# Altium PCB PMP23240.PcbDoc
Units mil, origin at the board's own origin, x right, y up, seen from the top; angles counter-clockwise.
Board outline 2210 x 1500 mil, 2 copper layers (Top Layer, Bottom Layer), stack 62 mil thick; 42 components, 17 nets, 93 pads, 30 vias.
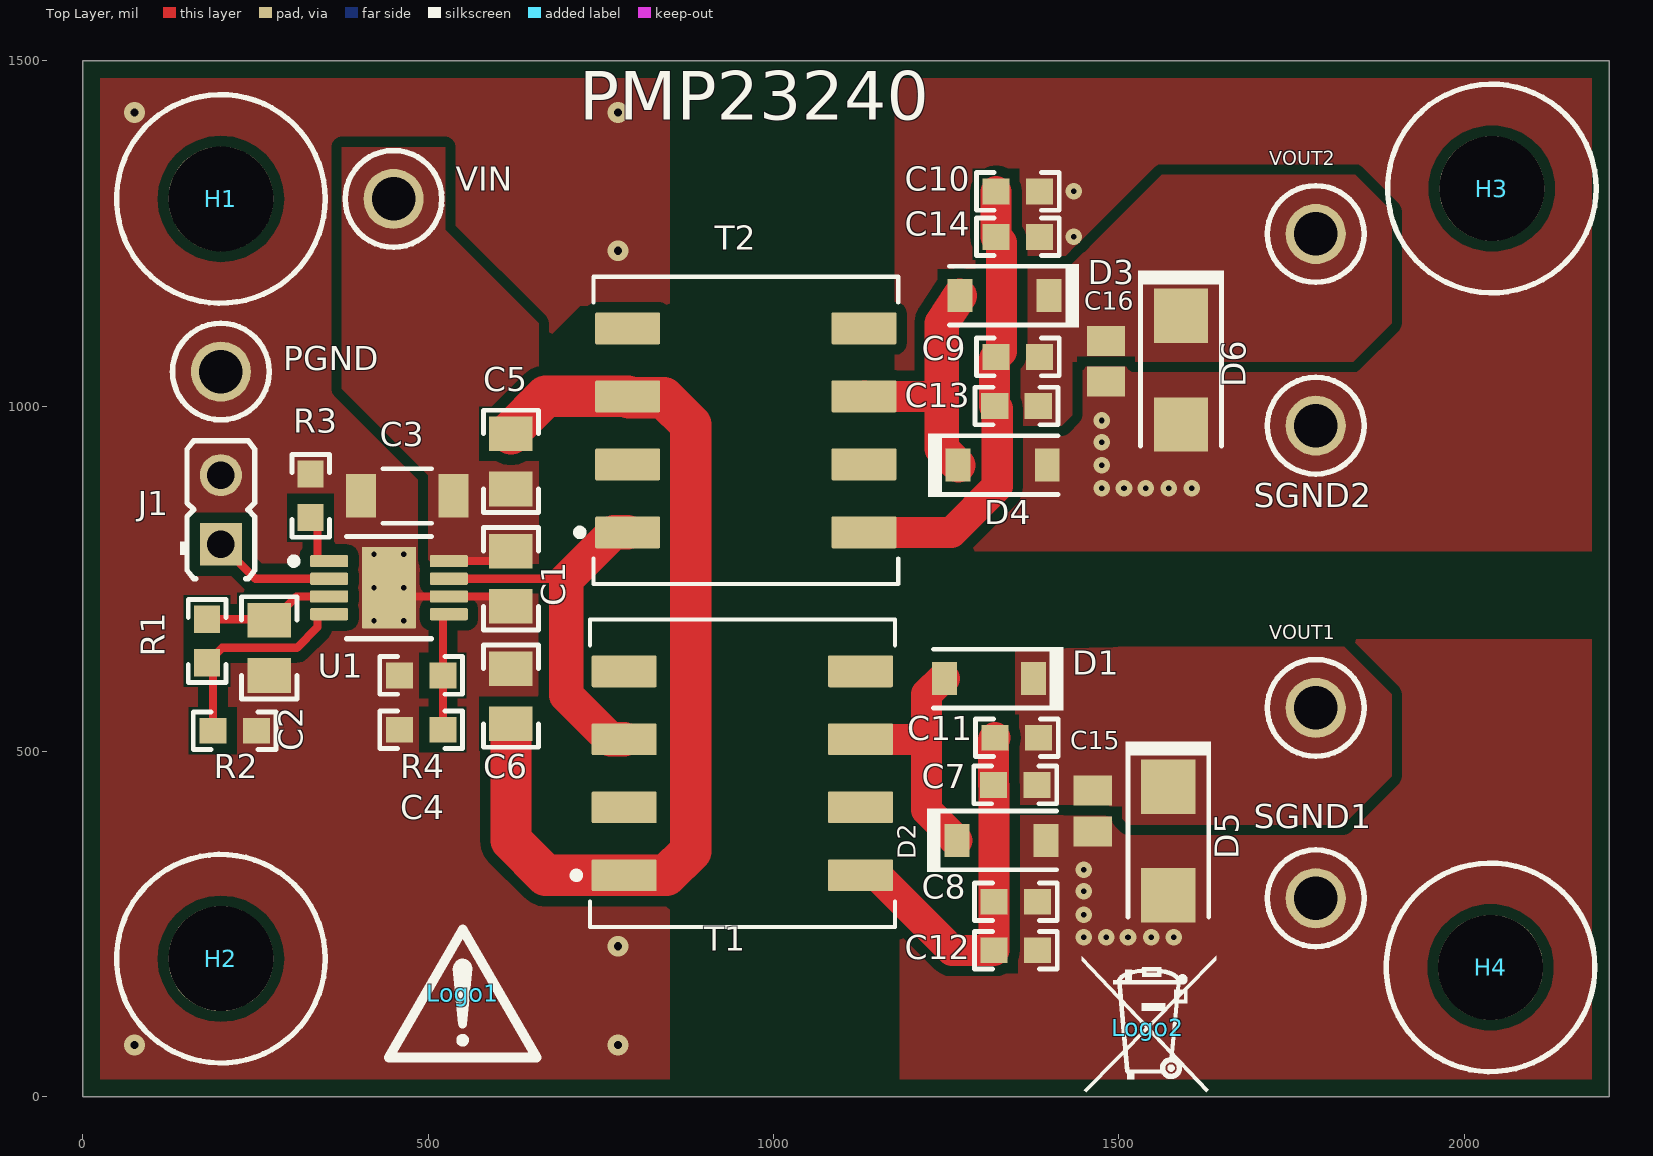
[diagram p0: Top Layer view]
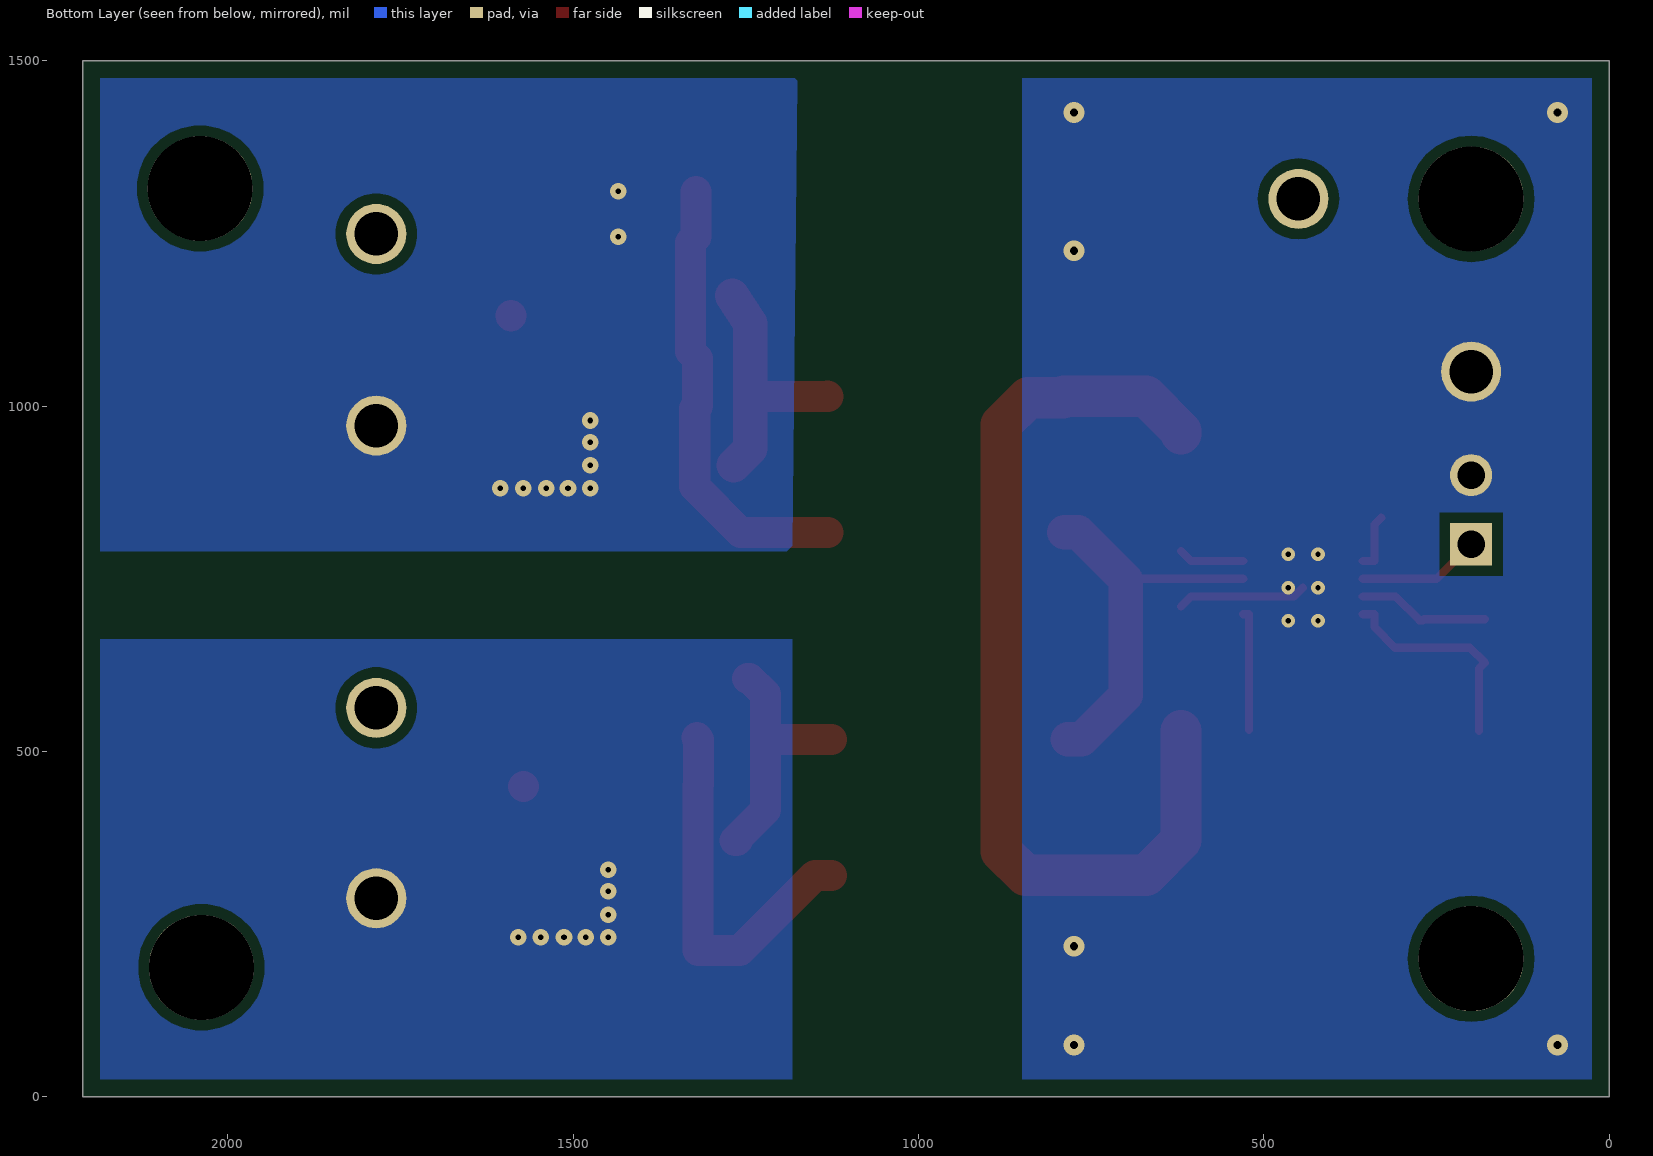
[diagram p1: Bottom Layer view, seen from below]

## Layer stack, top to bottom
Top Solder: solder mask 0.4, Solder Resist, Dk 3.5
Top Layer: signal copper 1.4
Dielectric1: core 59.2, FR-4 High Tg, Dk 4.8
Bottom Layer: signal copper 1.4
Bottom Solder: solder mask 0.4, Solder Resist, Dk 3.5

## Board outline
0,0 0,1500 2210,1500 2210,0

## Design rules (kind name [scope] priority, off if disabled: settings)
AcuteAngle [All] p1: minimum=4.50000000000000E+0001 checktracksonly=FALSE
AssemblyTestPointUsage [All] p1: valid=2
BoardOutlineClearance BoardOutlineClearance_MountingHoles [OnCopper and InComponentClass('Mounting Holes')] p1: gap=25 ignorepadtopadclearanceinfootprint=FALSE
BoardOutlineClearance BoardOutlineClearance_Poly [OnCopper and InPoly] p2: gap=25 ignorepadtopadclearanceinfootprint=FALSE
BoardOutlineClearance [OnCopper and Not InComponentClass('Logo') and not InComponentClass('FiducialMark') and not InRegion(1000,500,4000,800)] p3: gap=25 ignorepadtopadclearanceinfootprint=FALSE
Clearance Clearance_2 [InNetClass('HV') vs Not InNetClass('HV')] p1: gap=60 ignorepadtopadclearanceinfootprint=FALSE
Clearance Clearance_1 [InNetClass('MV') vs Not InNetClass('MV')] p2: gap=30 ignorepadtopadclearanceinfootprint=FALSE
Clearance Clearance_Keepouts [((IsTrack Or IsArc) And Not InPoly) And IsFree and IsKeepOut vs ((IsTrack Or IsArc) And Not InPoly) And IsFree and IsKeepOut] p3: gap=0 ignorepadtopadclearanceinfootprint=FALSE
Clearance Clearance_BoardEdge_MountingHoles [OnCopper and InComponentClass('Mounting Holes') vs IsKeepOut] p4: gap=40 ignorepadtopadclearanceinfootprint=FALSE except(0: Arc-Hole Track-Hole SMDPad-Hole THPad-Hole Via-Hole Fill-Hole Poly-Hole Region-Hole Text-Hole)
Clearance Clearance_BoardEdge_Poly [OnCopper and InPoly vs IsKeepOut] p5: gap=50 ignorepadtopadclearanceinfootprint=FALSE except(0: Arc-Hole Track-Hole SMDPad-Hole THPad-Hole Via-Hole Fill-Hole Poly-Hole Region-Hole Text-Hole)
Clearance Clearance_BoardEdge [OnCopper and Not InComponentClass('Logo') and not InComponentClass('FiducialMark') and not InRegion(1000,500,4000,800) and Not IsKeepout vs IsKeepOut] p6: gap=50 ignorepadtopadclearanceinfootprint=FALSE
Clearance Clearance_Poly [InPolygon] p7: gap=15 ignorepadtopadclearanceinfootprint=FALSE
Clearance [All] p8: gap=7.87 ignorepadtopadclearanceinfootprint=FALSE except(0: Arc-Hole Track-Hole SMDPad-Hole THPad-Hole Via-Hole Fill-Hole Poly-Hole Region-Hole Text-Hole)
ComponentClearance ComponentClearance_MountingHoles_FiducialMarks [InComponentClass('Mounting Holes') vs InComponentClass('FiducialMark')] p1: gap=20 collisioncheckmode=3 verticalgap=10 showdistances=FALSE
ComponentClearance ComponentClearance_Shunt [InComponentClass('Header') vs InComponentClass('Shunt')] p2: gap=0 collisioncheckmode=3 verticalgap=0 showdistances=FALSE
ComponentClearance ComponentClearance_Logo [InComponentClass('Logo')] p3: gap=5 collisioncheckmode=3 verticalgap=10 showdistances=FALSE
ComponentClearance ComponentClearance_ScrewToNut [(HasFootprint('NY PMS 440 0025 PH')) vs (HasFootprint('Keystone_1902C'))] p4: gap=20 collisioncheckmode=3 verticalgap=100000 showdistances=FALSE
ComponentClearance ComponentClearance_MountingHoles [InComponentClass('Mounting Holes')] p5: gap=20 collisioncheckmode=3 verticalgap=10 showdistances=FALSE
ComponentClearance ComponentClearance_SmallPassives [HasFootprint('0201*') or HasFootprint('0402*') or HasFootprint('0508') or HasFootprint('0603*') or HasFootprint('0612') or HasFootprint('0805*') or HasFootprint('0815*') or HasFootprint('0830*') or HasFootprint('1206*') or HasFootprint('1210*') or HasFootprint('1808*') or HasFootprint('1812*') or HasFootprint('1825*') or HasFootprint('2010*') or HasFootprint('2220*') or HasFootprint('2225*') or HasFootprint('2512*') or HasFootprint('2728*') or HasFootprint('3518*') vs HasFootprint('0201*') or HasFootprint('0402*') or HasFootprint('0508') or HasFootprint('0603*') or HasFootprint('0612') or HasFootprint('0805*') or HasFootprint('0815*') or HasFootprint('0830*') or HasFootprint('1206*') or HasFootprint('1210*') or HasFootprint('1808*') or HasFootprint('1812*') or HasFootprint('1825*') or HasFootprint('2010*') or HasFootprint('2220*') or HasFootprint('2225*') or HasFootprint('2512*') or HasFootprint('2728*') or HasFootprint('3518*')] p6: gap=20 collisioncheckmode=3 verticalgap=20 showdistances=FALSE
ComponentClearance ComponentClearance_THtoSMT [IsThruComponent vs IsSMTComponent] p7: gap=10 collisioncheckmode=3 verticalgap=10 showdistances=FALSE
ComponentClearance ComponentClearance_THtoTH [IsThruComponent vs IsThruComponent] p8: gap=10 collisioncheckmode=3 verticalgap=10 showdistances=FALSE
ComponentClearance [All] p9: gap=10 collisioncheckmode=3 verticalgap=10 showdistances=FALSE
DiffPairsRouting [All] p1: maxlimit=100 minlimit=10 mostfreqgap=10 toplayer_minwidth=15 toplayer_maxwidth=15 toplayer_prefwidth=15 bottomlayer_minwidth=15 bottomlayer_maxwidth=15 bottomlayer_prefwidth=15 maxuncoupledlength=1000
FabricationTestPointUsage TestPointUsage [All] p1: valid=2 allowmultiple=FALSE
FabricationTestpoint Testpoint [All] p1: side=3 testpointundercomponent=TRUE minsize=40 maxsize=100 preferedsize=60 minholesize=0 maxholesize=40 preferedholesize=32 testpointgrid=1 allowsidetop=TRUE allowsidebottom=TRUE usegrid=TRUE gridtolerance=0.01
FanoutControl Fanout_LCC [IsLCC] p1: bgadir=Out bgaviamode=Centered fanoutstyle=Auto fanoutdirection=Alternating viagrid=1 // Fanout_LCC (Default Rule)
FanoutControl Fanout_BGA [IsBGA] p2: bgadir=Out bgaviamode=Centered fanoutstyle=Auto fanoutdirection=Alternating viagrid=1 // Fanout_BGA (Default Rule)
FanoutControl Fanout_Default [All] p4: bgadir=Out bgaviamode=Centered fanoutstyle=Auto fanoutdirection=Alternating viagrid=1 // Fanout_Default (Default Rule)
FanoutControl Fanout_Small [(CompPinCount < 5)] p5: bgadir=Out bgaviamode=Centered fanoutstyle=Auto fanoutdirection=OutThenIn viagrid=1 // Fanout_Small (Default Rule)
Height [All] p1: minheight=0 maxheight=3000 prefheight=500
HoleSize [All] p1: absolutevalues=TRUE maxlimit=251 minlimit=7.87 maxpercent=80.000 minpercent=20.000
MinimumAnnularRing MinimumAnnularRing_ThermalPadVias [IsVia and InAnyComponent] p1: minimumring=5.91
MinimumAnnularRing [All] p2: minimumring=8
MinimumSolderMaskSliver MinimumSolderMaskSliver_Logo [InComponentClass('Logo') vs InComponentClass('Logo')] p1: minsoldermaskwidth=0.7
MinimumSolderMaskSliver [All] p2: minsoldermaskwidth=3.94
PlaneConnect [All] p1: planeconnectstyle=Direct reliefexpansion=10 reliefentries=4 reliefconductorwidth=10 reliefairgap=10
PolygonConnect PolygonConnect_15 [All vs IsNamedPolygon('C109_2') Or  IsNamedPolygon('C107_2') Or  IsNamedPolygon('HV') Or  IsNamedPolygon('Q203_5') Or  IsNamedPolygon('C107_2') Or  IsNamedPolygon('HS') Or  IsNamedPolygon('Q201_5') Or  IsNamedPolygon('Q203_5') Or  IsNamedPolygon('C106_2') Or  IsNamedPolygon('C108_2') Or  IsNamedPolygon('Vout') Or  IsNamedPolygon('Q203_5') Or  IsNamedPolygon('C108_2') Or  IsNamedPolygon('C113_2') Or  IsNamedPolygon('Q203_5') Or  IsNamedPolygon('Q201_5') Or  IsNamedPolygon('C107_2') Or  IsNamedPolygon('C102_1') Or  IsNamedPolygon('SGND') Or  IsNamedPolygon('GND') Or  IsNamedPolygon('SGND') Or  IsNamedPolygon('GND') Or  IsNamedPolygon('IN+') Or  IsNamedPolygon('IN+') Or  IsNamedPolygon('Q201_5') Or  IsNamedPolygon('Q201_5') Or  IsNamedPolygon('SGND') Or  IsNamedPolygon('SGND') Or  IsNamedPolygon('Vout') Or  IsNamedPolygon('Vout') Or  IsNamedPolygon('IN+') Or  IsNamedPolygon('GND') Or  IsNamedPolygon('IN+') Or  IsNamedPolygon('GND')] p1: connectstyle=Direct reliefconductorwidth=10 reliefentries=4 polygonreliefangle="90 Angle" airgapwidth=10
PolygonConnect PolygonConnect_14 [All vs IsNamedPolygon('C106_2') Or  IsNamedPolygon('C107_2') Or  IsNamedPolygon('C107_2') Or  IsNamedPolygon('C107_2') Or  IsNamedPolygon('C102_1') Or  IsNamedPolygon('Q203_5') Or  IsNamedPolygon('Vout') Or  IsNamedPolygon('Q203_5') Or  IsNamedPolygon('Q203_5') Or  IsNamedPolygon('Q201_5') Or  IsNamedPolygon('C108_2') Or  IsNamedPolygon('Q203_5') Or  IsNamedPolygon('HS') Or  IsNamedPolygon('HV') Or  IsNamedPolygon('C108_2') Or  IsNamedPolygon('Q201_5') Or  IsNamedPolygon('C109_2') Or  IsNamedPolygon('Q201_5') Or  IsNamedPolygon('Q201_5') Or  IsNamedPolygon('C113_2')] p2: connectstyle=Direct reliefconductorwidth=10 reliefentries=4 polygonreliefangle="90 Angle" airgapwidth=10
PolygonConnect PolygonConnect_13 [All vs IsNamedPolygon('C102_1') Or  IsNamedPolygon('HV') Or  IsNamedPolygon('C107_2') Or  IsNamedPolygon('C109_2') Or  IsNamedPolygon('C107_2') Or  IsNamedPolygon('C108_2') Or  IsNamedPolygon('C106_2') Or  IsNamedPolygon('C108_2') Or  IsNamedPolygon('C113_2') Or  IsNamedPolygon('C107_2')] p3: connectstyle=Direct reliefconductorwidth=10 reliefentries=4 polygonreliefangle="90 Angle" airgapwidth=10
PolygonConnect PolygonConnect_12 [All vs IsNamedPolygon('C107_2') Or  IsNamedPolygon('C113_2') Or  IsNamedPolygon('C106_2') Or  IsNamedPolygon('C107_2') Or  IsNamedPolygon('C107_2') Or  IsNamedPolygon('C102_1')] p4: connectstyle=Direct reliefconductorwidth=10 reliefentries=4 polygonreliefangle="90 Angle" airgapwidth=10
PolygonConnect PolygonConnect_11 [All vs IsNamedPolygon('C106_2') Or  IsNamedPolygon('C102_1') Or  IsNamedPolygon('C107_2') Or  IsNamedPolygon('C107_2') Or  IsNamedPolygon('C107_2')] p5: connectstyle=Direct reliefconductorwidth=10 reliefentries=4 polygonreliefangle="90 Angle" airgapwidth=10
PolygonConnect PolygonConnect_10 [All vs IsNamedPolygon('C106_2')] p6: connectstyle=Direct reliefconductorwidth=10 reliefentries=4 polygonreliefangle="90 Angle" airgapwidth=10
PolygonConnect PolygonConnect_9 [All vs IsNamedPolygon('C11_1') Or  IsNamedPolygon('Vin') Or  IsNamedPolygon('Vin') Or  IsNamedPolygon('5V') Or  IsNamedPolygon('D6_2') Or  IsNamedPolygon('Q3_3') Or  IsNamedPolygon('GND2') Or  IsNamedPolygon('GND2') Or  IsNamedPolygon('GND') Or  IsNamedPolygon('Q3_4') Or  IsNamedPolygon('12V5') Or  IsNamedPolygon('GND') Or  IsNamedPolygon('12V5') Or  IsNamedPolygon('D3_1')] p7: connectstyle=Direct reliefconductorwidth=10 reliefentries=4 polygonreliefangle="90 Angle" airgapwidth=10
PolygonConnect PolygonConnect_8 [All vs IsNamedPolygon('C11_1') Or  IsNamedPolygon('Vin') Or  IsNamedPolygon('12V5') Or  IsNamedPolygon('Q3_3') Or  IsNamedPolygon('GND2') Or  IsNamedPolygon('GND2') Or  IsNamedPolygon('5V') Or  IsNamedPolygon('Q3_4') Or  IsNamedPolygon('12V5')] p8: connectstyle=Direct reliefconductorwidth=10 reliefentries=4 polygonreliefangle="90 Angle" airgapwidth=10
PolygonConnect PolygonConnect_7 [All vs IsNamedPolygon('GND2') Or  IsNamedPolygon('GND2') Or  IsNamedPolygon('5V') Or  IsNamedPolygon('12V5') Or  IsNamedPolygon('12V5') Or  IsNamedPolygon('C11_1')] p9: connectstyle=Direct reliefconductorwidth=10 reliefentries=4 polygonreliefangle="90 Angle" airgapwidth=10
PolygonConnect PolygonConnect_6 [All vs IsNamedPolygon('GND2') Or  IsNamedPolygon('SGND') Or  IsNamedPolygon('GND1') Or  IsNamedPolygon('C901_1') Or  IsNamedPolygon('SGND') Or  IsNamedPolygon('GND2') Or  IsNamedPolygon('GND1')] p10: connectstyle=Direct reliefconductorwidth=10 reliefentries=4 polygonreliefangle="90 Angle" airgapwidth=10
PolygonConnect PolygonConnect_5 [All vs IsNamedPolygon('GND1') Or  IsNamedPolygon('GND1')] p11: connectstyle=Direct reliefconductorwidth=10 reliefentries=4 polygonreliefangle="90 Angle" airgapwidth=10
PolygonConnect PolygonConnect_4 [All vs IsNamedPolygon('C21_1') Or  IsNamedPolygon('C5_1') Or  IsNamedPolygon('C12_2') Or  IsNamedPolygon('C2_2') Or  IsNamedPolygon('C13_1') Or  IsNamedPolygon('C28_1') Or  IsNamedPolygon('C6_1') Or  IsNamedPolygon('GND') Or  IsNamedPolygon('GND2') Or  IsNamedPolygon('C14_1') Or  IsNamedPolygon('C13_1') Or  IsNamedPolygon('Q1_3') Or  IsNamedPolygon('C14_1') Or  IsNamedPolygon('C5_1') Or  IsNamedPolygon('GND2') Or  IsNamedPolygon('C28_1') Or  IsNamedPolygon('D5_2') Or  IsNamedPolygon('D6_2') Or  IsNamedPolygon('D2_1') Or  IsNamedPolygon('C12_2') Or  IsNamedPolygon('D2_1') Or  IsNamedPolygon('C4_1') Or  IsNamedPolygon('C4_1') Or  IsNamedPolygon('C2_2') Or  IsNamedPolygon('GND') Or  IsNamedPolygon('C33_1') Or  IsNamedPolygon('C9_1')] p12: connectstyle=Direct reliefconductorwidth=10 reliefentries=4 polygonreliefangle="90 Angle" airgapwidth=10
PolygonConnect PolygonConnect_3 [All vs IsNamedPolygon('C28_1') Or  IsNamedPolygon('C12_2') Or  IsNamedPolygon('C28_1') Or  IsNamedPolygon('C9_1') Or  IsNamedPolygon('D5_2') Or  IsNamedPolygon('C12_2') Or  IsNamedPolygon('C2_2') Or  IsNamedPolygon('C14_1') Or  IsNamedPolygon('C4_1') Or  IsNamedPolygon('C14_1') Or  IsNamedPolygon('D6_2') Or  IsNamedPolygon('GND2') Or  IsNamedPolygon('Q1_3') Or  IsNamedPolygon('C5_1') Or  IsNamedPolygon('D2_1') Or  IsNamedPolygon('C4_1') Or  IsNamedPolygon('C13_1') Or  IsNamedPolygon('C5_1') Or  IsNamedPolygon('C13_1') Or  IsNamedPolygon('C33_1') Or  IsNamedPolygon('D2_1') Or  IsNamedPolygon('GND') Or  IsNamedPolygon('GND') Or  IsNamedPolygon('GND2') Or  IsNamedPolygon('C2_2') Or  IsNamedPolygon('C6_1') Or  IsNamedPolygon('C21_1')] p13: connectstyle=Direct reliefconductorwidth=10 reliefentries=4 polygonreliefangle="90 Angle" airgapwidth=10
PolygonConnect PolygonConnect_2 [All vs IsNamedPolygon('C21_1') Or  IsNamedPolygon('C4_1') Or  IsNamedPolygon('D5_2') Or  IsNamedPolygon('C5_1') Or  IsNamedPolygon('C14_1') Or  IsNamedPolygon('C13_1') Or  IsNamedPolygon('C4_1') Or  IsNamedPolygon('C33_1') Or  IsNamedPolygon('C12_2') Or  IsNamedPolygon('D2_1') Or  IsNamedPolygon('C2_2') Or  IsNamedPolygon('C28_1') Or  IsNamedPolygon('C12_2') Or  IsNamedPolygon('D2_1') Or  IsNamedPolygon('C5_1') Or  IsNamedPolygon('Q1_3') Or  IsNamedPolygon('GND') Or  IsNamedPolygon('D6_2') Or  IsNamedPolygon('C6_1') Or  IsNamedPolygon('C2_2') Or  IsNamedPolygon('C14_1') Or  IsNamedPolygon('C28_1') Or  IsNamedPolygon('C13_1') Or  IsNamedPolygon('C9_1') Or  IsNamedPolygon('GND')] p14: connectstyle=Direct reliefconductorwidth=10 reliefentries=4 polygonreliefangle="90 Angle" airgapwidth=10
PolygonConnect PolygonConnect_1 [All vs IsNamedPolygon('C28_1') Or  IsNamedPolygon('D5_2') Or  IsNamedPolygon('C5_1') Or  IsNamedPolygon('C5_1') Or  IsNamedPolygon('D2_1') Or  IsNamedPolygon('C21_1') Or  IsNamedPolygon('C9_1') Or  IsNamedPolygon('C4_1') Or  IsNamedPolygon('C14_1') Or  IsNamedPolygon('C28_1') Or  IsNamedPolygon('C6_1') Or  IsNamedPolygon('C12_2') Or  IsNamedPolygon('C33_1') Or  IsNamedPolygon('C4_1') Or  IsNamedPolygon('C13_1') Or  IsNamedPolygon('C12_2') Or  IsNamedPolygon('D6_2') Or  IsNamedPolygon('C2_2') Or  IsNamedPolygon('C14_1') Or  IsNamedPolygon('D2_1') Or  IsNamedPolygon('C2_2') Or  IsNamedPolygon('C13_1')] p15: connectstyle=Direct reliefconductorwidth=10 reliefentries=4 polygonreliefangle="90 Angle" airgapwidth=10
PolygonConnect [All] p16: connectstyle=Direct reliefconductorwidth=10 reliefentries=4 polygonreliefangle="90 Angle" airgapwidth=10
RoutingVias ThermalPadVias [IsVia and InAnyComponent] p1: holewidth=7.87 width=19.68 viastyle="Through Hole" minholewidth=7.87 minwidth=19.68 maxholewidth=12.99 maxwidth=23.62
RoutingVias [All] p2: holewidth=16 width=34 viastyle="Through Hole" minholewidth=7.87 minwidth=20 maxholewidth=40 maxwidth=65
SilkToBoardRegionClearance [Not ((IsComment or IsDesignator) And (Hide <> 'False')) and not InRegion(1000,500,4000,800)] p1:
SilkToSilkClearance SilkToSilkClearance_Pb-FreeLogo [(HasFootprint('Pb-Free_Overlay_Medium') OR HasFootprint('Pb-Free_Overlay_Small')) vs (HasFootprint('Pb-Free_Overlay_Medium') OR HasFootprint('Pb-Free_Overlay_Small'))] p1: silktosilkclearance=0
SilkToSilkClearance [All] p2: silktosilkclearance=4
SilkToSolderMaskClearance SilkToComponentPadClearance [IsPad and InAnycomponent] p1: minsilkscreentomaskgap=5 clearancetoexposedcopper=TRUE
SilkToSolderMaskClearance "Silk to Solder Mask Opening" [All] p2: minsilkscreentomaskgap=4 clearancetoexposedcopper=FALSE
SolderMaskExpansion [All] p1: expansion=1.97 istentingtop=FALSE
Width [All] p1: maxlimit=100 minlimit=6 preferedwidth=10 checkconnectedcopper=TRUE
14 further rules are at their usual default settings.

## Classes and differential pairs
component class Header: J1

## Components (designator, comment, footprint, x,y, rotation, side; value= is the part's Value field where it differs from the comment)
C1 "GRM219R7YA105KA12D" 0805_HV 620,750 r270 top value=1uF
C2 "GRM219R7YA105KA12D" 0805_HV 270,650 r270 top value=1uF
C3 "GRM31CR71H475KA12L" 1206_180 470,870 r180 top value=4.7uF
C4 "GRM1885C1H101JA01D" 0603 490,531.49 r180 top value=100pF
C5 "GRM219R7YA105KA12D" 0805_HV 620,920 r90 top value=1uF
C6 "GRM219R7YA105KA12D" 0805_HV 620,580 r90 top value=1uF
C7 "GRM188R71H223KA01D" 0603 1350.01,451.53 r0 top value=0.022uF
C8 "GRM188R71H223KA01D" 0603 1350.85,282.38 r180 top value=0.022uF
C9 "GRM188R71H223KA01D" 0603 1353.7,1071.07 r0 top value=0.022uF
C10 "GRM188R71H223KA01D" 0603 1353.7,1310.78 r180 top value=0.022uF
C11 "GRM188R71H103KA01D" 0603 1352.4,519.88 r180 top value=0.01uF
C12 "GRM188R71H103KA01D" 0603 1350.85,212.15 r0 top value=0.01uF
C13 "GRM188R71H103KA01D" 0603 1351.74,1000.19 r180 top value=0.01uF
C14 "GRM188R71H103KA01D" 0603 1353.7,1245 r0 top value=0.01uF
C15 "GRM21BZ71E106KE15L" 0805L 1462.2,413.73 r270 top value=10uF
C16 "GRM21BZ71E106KE15L" 0805L 1481.34,1064.9 r270 top value=10uF
D1 "PMEG6010CEGWJ" SOD-123 1311.88,605.59 r180 top value=60V
D2 "PMEG6010CEGWJ" SOD-123 1330.09,371.23 r0 top value=60V
D3 "PMEG6010CEGWJ" SOD-123 1334.47,1160 r180 top value=60V
D4 "PMEG6010CEGWJ" SOD-123 1331.87,914.61 r0 top value=60V
D5 "SMAZ18-13-F" SMA 1571.61,370.42 r270 top value=18V
D6 "SMAZ18-13-F" SMA 1590.01,1052.07 r270 top value=18V
H1 "4824" KEYSTONE_4824 200,1300 r0 top
H2 "4824" KEYSTONE_4824 200,200 r0 top
H3 "4824" KEYSTONE_4824 2040,1315 r0 top
H4 "4824" KEYSTONE_4824 2038.17,187.5 r0 top
J1 "22284023" Molex_0022284023 200,850 r90 top
Logo1 "" IEC_Caution_Small 550,150 r0 top
Logo2 "WEEE logo" WEEE_Minimum 1541.5,100 r0 top
PGND "5011" Keystone5011 200,1050 r90 top
R1 "CRCW06033K24FKEA" 0603 180,660 r90 top value=3.24k
R2 "CRCW060311K0FKEA" 0603 220,530 r180 top value=11.0k
R3 "CRCW060310K0FKEA" 0603 330,870 r270 top value=10.0k
R4 "CRCW060360K4FKEA" 0603 490,610 r0 top value=60.4k
SGND1 "5011" Keystone5011 1785,287.45 r90 top
SGND2 "5011" Keystone5011 1785,971.64 r90 top
T1 "750319177r02" FP-750319177r02_SMT_11MM21_11MM3-MFG 955,468.36 r0 top
T2 "750319177r02" FP-750319177r02_SMT_11MM21_11MM3-MFG 960,964.8 r0 top
U1 "UCC25800DGNRQ1" DGN0008G-MFG 443.39,737.2 r0 top
VIN "5010" Keystone5010 450,1300 r0 top
VOUT1 "5010" Keystone5010 1785,563.09 r0 top
VOUT2 "5010" Keystone5010 1785,1249.2 r0 top

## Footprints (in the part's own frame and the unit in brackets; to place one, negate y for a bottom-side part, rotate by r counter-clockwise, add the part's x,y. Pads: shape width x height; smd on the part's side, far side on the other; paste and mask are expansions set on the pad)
0603 [mm] "0603 from SM-752 data"
  rect 1x0.95 smd: 1(-0.8,0) 2(0.8,0)
  silkscreen extent -1.52,-0.69 1.52,0.69, body extent -0.87,-0.47 0.87,0.47, height 1
0805_HV [mil] "0805 with 30mil clearance between pads"
  rect 50x63 smd: 1(-40,0) 2(40,0)
  silkscreen extent -74,-40 74,40, body extent -43,-29 43,29, height 57
0805L [mm] "0805 from SM-752 data"
  rect 1.1x1.4 smd: 1(-0.75,0) 2(0.75,0)
  body extent -1.1,-0.72 1.1,0.72, height 1.45
1206_180 [mm] "1206_180"
  rect 1.1x1.6 smd: 1(-1.7,0) 2(1.7,0)
  silkscreen extent -0.9,-1 0.9,1, body extent -1.75,-0.95 1.75,0.95, height 1.8
DGN0008G-MFG [mm]
  rrect22% 1.4x0.45 smd paste+0 mask+0: 1(-2.2,0.975) 2(-2.2,0.325) 3(-2.2,-0.325) 4(-2.2,-0.975) 5(2.2,-0.975) 6(2.2,-0.325) 7(2.2,0.325) 8(2.2,0.975)
  rrect5% 2x3 smd paste-1000 mask-1000: 9(0,0)
  silkscreen extent -3.62,-1.88 1.55,1.88, body extent -3,-1.8 3,1.8, height 0.25
FP-750319177r02_SMT_11MM21_11MM3-MFG [mm]
  rrect9% 2.39x1.17 smd paste+0 mask+0: 1(-4.345,-3.75) 2(-4.345,-1.25) 3(-4.345,1.25) 4(-4.345,3.75) 5(4.345,3.75) 6(4.345,1.25) 7(4.345,-1.25) 8(4.345,-3.75)
  silkscreen extent -6.23,-5.65 5.61,5.65, body extent -5.71,-5.75 5.71,5.75, height 0.25
IEC_Caution_Small [mil]
  silkscreen extent -107,-93 107,92
Keystone5010 [mil] "Keystone Multipurpose loops"
  round 87 hole 63: 1(0,0)
  silkscreen extent -70,-70 70,70, body extent -63,-63 63,62, height 319
Keystone5011 [mil] "Keystone Multipurpose loops"
  round 87 hole 63: 1(0,0)
  silkscreen extent -70,-70 70,70, body extent -63,-63 63,62, height 319
KEYSTONE_4824 [mil] "HEX STANDOFF 6-32 NYLON 1-1/2\""
  round 1 on Mech3: 0(0,0)
  round 152 hole 152 unplated: MH(0,0)
  silkscreen extent -151,-151 151,151, body extent -144,-125 144,125, height 1500
Molex_0022284023 [mm] "Header, 2.54mm, 2x1, TH"
  rect 1.55x1.55 hole 1.02: 1(-1.27,0)
  round 1.55 hole 1.02: 2(1.27,0)
  silkscreen extent -2.54,-1.24 2.54,1.5, body extent -2.54,-1.24 2.54,1.24, height 8.4
SMA [mm] "Molded Diode, 2-Leads, Body 4.3x2.6mm, IPC Medium Density, based on OnSemi component dimensions and land pattern"
  rect 2x2 smd: 1(-2,0) 2(2,0)
  silkscreen extent -3.66,-1.57 2.79,1.57, body extent -2.6,-1.3 2.6,1.3, height 2.42
SOD-123 [mm] "On Semi recommended land pattern"
  rect 0.915x1.22 smd: 1(-1.637,0) 2(1.637,0)
  silkscreen extent -2.74,-1.17 2.03,1.17, body extent -1.93,-0.9 1.93,0.9, height 1.35
WEEE_Minimum [mil] "WEEElie bin"
  silkscreen extent -95,-94 99,104

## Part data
C1 C2 C5 C6: library part CMP-0085980-1, "CAP, CERM, 1 µF, 35 V,+/- 10%, X7R, 0805", Cap_Case=0805, Manufacturer=MuRata, TempCo=X7R, Tolerance_%=10%, Value2=35V, ValueDisplayed=1µF
C3: library part CMP-0008969-2, "CAP, CERM, 4.7 uF, 50 V, +/- 10%, X7R, 1206", Cap_Case=2220, Manufacturer=MuRata, Supplier Part Number 1=24R6347, TempCo=X7R, Tolerance_%=10%, Value1=Unknown, Value2=50V, ValueDisplayed=4.7uF
C4: library part CMP-0007171-4, "CAP, CERM, 100 pF, 50 V, +/- 5%, C0G/NP0, 0603", Cap_Case=0603, Manufacturer=MuRata, Supplier Part Number 1=490-1427-1-ND, TempCo=C0G/NP0, Tolerance_%=5%, Value1=Unknown, Value2=50V, ValueDisplayed=100pF
C7 C8 C9 C10: library part CMP-0007444-5, "CAP, CERM, 0.022 uF, 50 V, +/- 10%, X7R, 0603", Cap_Case=0603, Manufacturer=MuRata, Supplier Part Number 1=490-1517-1-ND, TempCo=X7R, Tolerance_%=10%, Value1=Unknown, Value2=50V, ValueDisplayed=0.022uF
C11 C12 C13 C14: library part CMP-0007433-4, "CAP, CERM, 0.01 uF, 50 V, +/- 10%, X7R, 0603", Cap_Case=0603, Manufacturer=MuRata, Supplier Part Number 1=490-1512-1-ND, TempCo=X7R, Tolerance_%=10%, Value1=Unknown, Value2=50V, ValueDisplayed=0.01uF
C15 C16: library part CMP-0008378-2, "CAP, CERM, 10 uF, 25 V, +/- 10%, X7R, 0805", Cap_Case=0805, Manufacturer=MuRata, Supplier Part Number 1=81-GRM21BZ71E106KE5L, TempCo=X7R, Tolerance_%=10%, Value1=Unknown, Value2=25V, ValueDisplayed=10uF
D1 D2 D3 D4: library part CMP-0079239-2, "Diode, Schottky, 60 V, 1 A, AEC-Q101, SOD-123", Manufacturer=Nexperia, Value1=1A, Value2=0.66V
D5 D6: library part CMP-0005526-4, "Diode, Zener, 18 V, 1 W, AEC-Q101, SMA", Manufacturer="Diodes Inc.", Power_W=1W
H1 H2 H3 H4: library part CMP-0003690-1, Manufacturer=Keystone, Supplier Part Number 1=36-4824-ND
J1: library part CMP-0055333-1, "Header, 2.54mm, 2x1, Tin, TH", Color=Black, Current_A=4A, Manufacturer=Molex, Supplier Part Number 1=WM50016-02-ND, Voltage_V=250V
Logo1: library part CMP-0074836-1, "IEC 61010-1 Caution Warning", PartNumber="CAUTION.  READ USER GUIDE BEFORE USE"
Logo2: library part CMP-0074769-1
PGND SGND1 SGND2: library part CMP-0055148-1, "Test Point, Multipurpose, Black, TH", Color=Black, Manufacturer=Keystone, Supplier Part Number 1=36-5011-ND
R1: library part CMP-0022374-4, "RES, 3.24 k, 1%, 0.1 W, AEC-Q200 Grade 0, 0603", Manufacturer=Vishay-Dale, Power_W=100mW, Supplier Part Number 1=541-3.24KHCT-ND, TempCo="100 ppm/C", Tolerance_%=1%, Value2=0.1W, Value_Code=3k24, ValueDisplayed=3.24k
R2: library part CMP-0022016-4, "RES, 11.0 k, 1%, 0.1 W, AEC-Q200 Grade 0, 0603", Manufacturer=Vishay-Dale, Power_W=100mW, Supplier Part Number 1=541-11.0KHCT-ND, TempCo="100 ppm/C", Tolerance_%=1%, Value2=0.1W, Value_Code=11k0, ValueDisplayed=11.0k
R3: library part CMP-0021998-4, "RES, 10.0 k, 1%, 0.1 W, AEC-Q200 Grade 0, 0603", Manufacturer=Vishay-Dale, Power_W=100mW, Supplier Part Number 1=541-10.0KHCT-ND, TempCo="100 ppm/C", Tolerance_%=1%, Value2=0.1W, Value_Code=10k0, ValueDisplayed=10.0k
R4: library part CMP-0022532-4, "RES, 60.4 k, 1%, 0.1 W, AEC-Q200 Grade 0, 0603", Manufacturer=Vishay-Dale, Power_W=100mW, Supplier Part Number 1=541-60.4KHCT-ND, TempCo="100 ppm/C", Tolerance_%=1%, Value2=0.1W, Value_Code=60k4, ValueDisplayed=60.4k
T1 T2: library part CMP-0091345-1, "Transformer, 1:1.67, 0.045Ohm Pri, 0.122Ohm Sec, 16.5uH", Frequency_Fixed=500kHz, Manufacturer="Wurth Electronics", Operating Temperature Range="-40°C to +125°C"
U1: library part CMP-0088494-2, "Open Loop LLC Transformer Driver for Isolated Bias Supplies", Manufacturer="Texas Instruments", Max Supply Voltage=36V, Min Supply Voltage=12V, Nominal Supply Current=500uA, Operating Temperature Range="-40°C to +150°C", Switching Frequency=100-2000kHz
VIN VOUT1 VOUT2: library part CMP-0055147-1, "Test Point, Multipurpose, Red, TH", Color=Red, Manufacturer=Keystone, Supplier Part Number 1=36-5010-ND

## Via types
v1: diameter 24, hole 8, Top Layer to Bottom Layer, tented both sides, 18 vias
v2: diameter 30, hole 12, Top Layer to Bottom Layer, tented top, 6 vias
v3: diameter 19.68, hole 7.87, Top Layer to Bottom Layer, 6 vias

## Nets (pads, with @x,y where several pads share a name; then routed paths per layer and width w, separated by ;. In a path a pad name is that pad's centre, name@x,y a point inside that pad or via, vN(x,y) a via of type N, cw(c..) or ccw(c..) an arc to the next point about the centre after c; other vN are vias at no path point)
+12V: C1.1 C3.1 C5.1 U1.8 VIN.1 | length 96
  Top Layer w12: U1.8 605.59,775.59 C1.1
NetC2_1: C2.1 R1.2 U1.3 | length 191.6
  Top Layer w12: R1.2 268.5,691.5 C2.1 275,690 309.41,724.41 U1.3
NetC4_1: C4.1 R4.2 U1.5 | length 175.8
  Top Layer w12: C4.1 521.5,698.82 U1.5
NetC5_2: C5.2 C6.1 T1.1 T2.3 | length 1373
  Top Layer w60: C6.1@620,530 620,371.23 670.51,320.72 T1.1 844.85,320.72 880,355.87 880,973.34 841.22,1012.12 790.83,1012.12 T2.3 670.51,1014.01 620,963.5 C5.2
NetC7_1: C7.1 C8.2 C11.2 C12.1 T1.8 | length 547.3
  Top Layer w45: T1.8 1150.08,320.72 1258.65,212.15 C12.1 C8.2 1319.36,450.68 C7.1 1318.51,517.49 C11.2
NetC7_2: C7.2 C11.1 C15.1 D1.1 D5.1 VOUT1.1 | length 0
NetC9_1: C9.1 C10.2 C13.2 C14.1 T2.8 | length 656.6
  Top Layer w45: T2.8 1257.66,817.16 1323.96,883.46 1323.96,996.47 C13.2 1320.24,1069.11 1330.09,1078.95 1330.09,1237.12 C14.1 C10.2
NetC9_2: C9.2 C13.1 C16.1 D3.1 D6.1 VOUT2.1 | length 0
NetD1_2: D1.2 D2.1 T1.6 | length 362.3
  Top Layer w45: T1.6 1221.76,517.57 ; D1.2 1244.44,605.59 1221.76,582.91 1221.76,517.57 ; D2.1 1262.65,371.23 1261.13,372.75 1261.13,375.72 1221.76,415.09 1221.76,517.57
NetD3_2: D3.2 D4.1 T2.6 | length 378.5
  Top Layer w45: T2.6@1131.59,1014.55 T2.6 1239,1014.01 1243.87,1018.89
  Top Layer w50: D4.1 1243.87,938.14 1243.87,1018.89 1243.87,1120.22 D3.2
NetJ1_1: J1.1 U1.2 | length 177.5
  Top Layer w12: J1.1 249.99,750 U1.2
NetR1_1: R1.1 R2.2 U1.4 | length 318.9
  Top Layer w12: R2.2 188.5,620 R1.1 201.5,650 310,650 340,680 340,698.82 U1.4
NetR3_2: R3.2 U1.1 | length 83.8
  Top Layer w12: R3.2 340,828.5 340,775.59 U1.1
NetT1_3: T1.3 T2.1 U1.7 | length 583.2
  Top Layer w12: U1.7 701.69,750 718.5,750
  Top Layer w50: T1.3 763.86,517.57 700,581.43 700,748.3 701.69,750 768.86,817.16 T2.1
PGND: C1.2 C2.2 C3.2 C4.2 C6.2 J1.2 PGND.1 R2.1 R3.1 R4.1 U1.6 U1.9 | length 187.9
  Top Layer w12: U1.9 456.18,724.41 U1.6 605.59,724.41 C1.2
  other v2: 75,75 775,75 775,217.84 775,1225 75,1425 775,1425
  other v3: 421.73,689.17 465.04,689.17 421.73,737.2 465.04,737.2 421.73,785.24 465.04,785.24
SGND1: C8.1 C12.2 C15.2 D2.2 D5.2 SGND1.1
  other v1: 1449.41,230.85 1481.89,230.85 1513.25,230.84 1546.94,230.84 1579.77,230.84 1449.41,263.68 1449.41,297.37 1449.42,328.73
SGND2: C10.1 C14.2 C16.2 D4.2 D6.2 SGND2.1
  other v1: 1474.99,881.26 1507.47,881.26 1538.83,881.25 1572.53,881.25 1605.35,881.25 1474.99,914.09 1474.99,947.78 1475,979.14 1435,1245 1435,1310.78
pads on no net: H1.0 H1.MH H2.0 H2.MH H3.0 H3.MH H4.0 H4.MH T1.2 T1.4 T1.5 T1.7 T2.2 T2.4 T2.5 T2.7

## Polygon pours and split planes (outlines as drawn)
SGND1 on Top Layer "TOP_LAYER_SGND1_P036" (solid, remove dead copper, pour order 36): 1183.17,662.59 1183.17,636.2 1183.17,0 2210,0 2210,662.59
SGND2 on Top Layer "TOP_LAYER_SGND2_P035" (solid, remove dead copper, pour order 35): 1175.67,1500 1175.67,805 1190.67,790 2210,790 2210,1500
NetC7_2 on Top Layer "TOP_LAYER_NETC7_2_P034" (solid, remove dead copper, pour order 34): 1495.72,651.59 1826.32,651.59 1895,582.91 1895,464.33 1824.72,394.05 1526.29,394.05
NetC9_2 on Top Layer "TOP_LAYER_NETC9_2_P033" (solid, remove dead copper, pour order 33): 1429.47,1202.5 1561.97,1335 1842.24,1335 1895,1282.24 1895,1120 1839,1064 1568.34,1064
NetC7_2 on Top Layer "TOP_LAYER_NETC7_2_P032" (solid, remove dead copper, pour order 32): 1353.7,648.09 1350.01,644.4 1350.01,422.98 1484.45,422.98 1513.39,394.05 1630.12,394.05 1630.12,547.76 1526.29,651.59
NetC9_2 on Top Layer "TOP_LAYER_NETC9_2_P031" (solid, remove dead copper, pour order 31): 1351.74,1202.68 1351.74,971.64 1417.21,971.64 1432.2,986.64 1432.2,1064 1658,1064 1658.9,1064.9 1658.9,1178.78 1635,1202.68
PGND on Top Layer "Top Layer-No Net 6" (solid, remove dead copper, pour order 2): 0,1500 850,1500 850,1145 720,1145 660,1085 660,415 720,355 850,355 850,0 0,0
+12V on Top Layer "Top Layer-No Net 6" (solid, remove dead copper, pour order 0): 375,1375 525,1375 525,1255 660,1120 660,760 500.08,760 500.08,899.91 375,1024.99
SGND1 on Bottom Layer "BOTTOM_LAYER_SGND1_P038" (solid, remove dead copper, pour order 38): 1183.17,25.49 2184.51,25.49 2184.51,662.59 1183.17,662.59
SGND2 on Bottom Layer "BOTTOM_LAYER_SGND2_P037" (solid, remove dead copper, pour order 37): 1175.67,1474.51 2184.51,1474.51 2184.51,790 1190.67,790 1183.17,797.5
PGND on Bottom Layer "Top Layer-No Net 6" (solid, remove dead copper, pour order 4): 0,1500 850,1500 850,0 0,0

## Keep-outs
Keep-Out Layer:
  text ".Layer_Name" at 577,-858.49 h60

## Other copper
Top Layer:
  text ".Layer_Name" at 577,-858.49 h60
Bottom Layer:
  text ".Layer_Name" at 577,-858.49 h60

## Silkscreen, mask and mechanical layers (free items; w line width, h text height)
Top Overlay:
  text "PMP23240" at 718.5,1391.44 h120
  text ".Layer_Name" at 577,-858.49 h60
Bottom Overlay:
  text ".Layer_Name" at 577,-858.49 h60
Top Paste:
  text ".Layer_Name" at 577,-858.49 h60
Bottom Paste:
  text ".Layer_Name" at 577,-858.49 h60
Top Solder:
  text ".Layer_Name" at 577,-858.49 h60
  text ".Layer_Name" at 577,-858.49 h60
Bottom Solder:
  text ".Layer_Name" at 577,-858.49 h60
Drill Guide:
  text ".Layer_Name" at 577,-858.49 h60
M1 Board Outline:
  the board outline again, w10
  text ".Layer_Name" at 577,-858.49 h60
M2 Board Dimensions:
  rectangle: 0,-275 125,-150
  rectangle: 125,-400 500,-275
  lines w7: 0,-275 1000,-275 ; 125,-400 125,-150 ; 250,-400 250,-150 ; 500,-400 500,-150 ; 750,-400 750,-150 ; 0,-400 1000,-400 1000,-150 0,-150 0,-400
  text ".Layer_Name" at 577,-858.49 h60
M3 3D STEP Top:
  text ".Layer_Name" at 577,-858.49 h60
M4 3D STEP Bottom:
  text ".Layer_Name" at 577,-858.49 h60
M5 Assembly Top:
  lines w10: -292,-930.17 6308,-930.17 ; -292,-726.83 6310,-726.83 ; -292,-523.5 -292,-1133.5 3713,-1133.5 6310,-1133.5 6310,-523.5 -291.5,-523.5 -291.5,-1133.5 1284,-1133.5 ; 2173,-1133.5 2173,-523.5 ; 3440,-726.83 3440,-523.5 ; 4280,-726.83 4280,-523.5 ; 4902,-1140 4902,-937.17
  text "COMPONENTS MARKED 'DNP' SHOULD NOT BE POPULATED." at 1153.5,-318.5 h60
  text "ASSEMBLY VARIANT:" at 1153,-434 h60
  text ".VariantName" at 2189,-434 h60
  text "PCB VIEWED FROM TOP SIDE" at -228.5,-655.67 h60
  text "BOARD #:" at 2248,-655.67 h60
  text ".PRJ_Number" at 2793.5,-655.67 h60
  text "REV:" at 3638,-655.67 h60
  text ".PCB_Rev" at 3929.5,-655.67 h60
  text "SVN REV:" at 4476,-655.67 h60
  text ".VersionControl_RevNumber" at 4982,-655.67 h60
  text "TID #:" at 2248,-859 h60
  text ".TID" at 2793.5,-859 h60
  text "PLOT NAME =" at -228.5,-1064.34 h60
  text ".plot_File_Name" at 577,-1064.34 h60
  text "GENERATED    :" at 2250,-1064.34 h60
  text ".Print_Date" at 3119.5,-1064.34 h60
  text ".Print_Time" at 3848.5,-1064.34 h60
  text "TEXAS INSTRUMENTS" at 5113,-1064.34 h60
M6 Assembly Bottom:
  lines w10: -292.5,-727.33 6309.5,-727.33 ; -290.5,-930.67 6309.5,-930.67 ; 1115.5,-1140.5 1115.5,-937.67 ; 1737.5,-727.33 1737.5,-524 ; 2577.5,-727.33 2577.5,-524 ; 3844.5,-1134 3844.5,-524 ; 4733.5,-1134 6309,-1134 6309,-524 -292.5,-524 -292.5,-1134 2304.5,-1134 6309.5,-1134 6309.5,-524
  text "COMPONENTS MARKED 'DNP' SHOULD NOT BE POPULATED." at 6102,-318 h60
  text ".VariantName" at 5058,-434 h60
  text "ASSEMBLY VARIANT:" at 6097,-434 h60
  text ".VersionControl_RevNumber" at 1035.5,-656.17 h60
  text "SVN REV:" at 1541.5,-656.17 h60
  text ".PCB_Rev" at 2088,-656.17 h60
  text "REV:" at 2379.5,-656.17 h60
  text ".PRJ_Number" at 3224,-656.17 h60
  text "BOARD #:" at 3769.5,-656.17 h60
  text "PCB VIEWED FROM BOTTOM SIDE" at 6246,-656.17 h60
  text ".TID" at 3224,-859.5 h60
  text "TID #:" at 3769.5,-859.5 h60
  text "TEXAS INSTRUMENTS" at 904.5,-1064.84 h60
  text ".Print_Time" at 2169,-1064.84 h60
  text ".Print_Date" at 2898,-1064.84 h60
  text "GENERATED    :" at 3767.5,-1064.84 h60
  text ".plot_File_Name" at 5440.5,-1064.84 h60
  text "PLOT NAME =" at 6246,-1064.84 h60
M9 Title Sheet:
  drawing of 57 lines, arcs and shapes, not listed
  text "1" at 739.84,8036.5 h70
  text "2" at 3235.5,8036.5 h70
  text "3" at 5724.84,8036.5 h70
  text "4" at 8231.51,8036.5 h70
  text "5" at 10730.5,8036.5 h70
  text "6" at 13235.5,8036.5 h70
  text "A" at -416.5,6893.5 h70
  text "A" at 14383.5,6893.5 h70
  text "B" at -416.5,4513.5 h70
  text "B" at 14383.5,4513.5 h70
  text "C" at -416.5,2138.5 h70
  text "C" at 14383.5,2138.5 h70
  text "PROJECT TITLE:" at 11343.5,277.5 h45
  text ".PRJ_Title" at 11393.5,144.17 h70
  text "DESIGNED FOR:" at 11343.5,-23.5 h45
  text ".PRJ_Customer" at 11393.5,-163.5 h70
  text "D" at -416.5,-231.5 h70
  text "D" at 14383.5,-231.5 h70
  text "FILE NAME:" at 11343.5,-323.5 h45
  text ".PCB_File_Name_No_Path" at 11393.5,-443.5 h70
  text "Texas Instruments (TI) and/or its licensors do not warrant the accuracy or completeness of this specification" at 6374,-605.34 h45
  text "ENGINEER:" at 11343.5,-613.5 h45
  text "LAYOUT BY:" at 12848.5,-613.5 h45
  text "or any information contained therein. TI and/or its licensors do not warrant that this design will meet" at 6329.01,-718 h45
  text ".PRJ_Engineer" at 11393.5,-768.49 h70
  text ".PCB_Layout" at 12899,-768.49 h70
  text "the specifications, will be suitable for your application or fit for any particular purpose, or will operate in" at 6329.01,-830.67 h45
  text ".Layer_Name" at 577,-858.49 h60
  text "ALTIUM DESIGNER VERSION:" at 12848.5,-923.5 h45
  text "an implementation. TI and/or its licensors do not warrant that the design is production worthy. You should" at 6329.01,-943.33 h45
  text "completely validate and test your design implementation to confirm the system functionality for your application." at 6374,-1056 h45
  text ".print_Scale" at 11393.5,-1056.83 h70
  text ".Application_BuildNumber" at 12899,-1056.83 h70
  text "1" at 739.84,-1263.5 h70
  text "2" at 3235.5,-1263.5 h70
  text "3" at 5724.84,-1263.5 h70
  text "4" at 8231.51,-1263.5 h70
  text "5" at 10730.5,-1263.5 h70
  text "6" at 13235.5,-1263.5 h70
M10 Fab Notes:
  drawing of 189 lines, arcs and shapes, not listed
  text "DESIGN INFORMATION" at 12382.02,6356.17 h60
  text "MIN. TRACK WIDTH:" at 11737.46,6224.05 h60
  text "8" at 12833.7,6224.05 h60
  text "MIL" at 12988.46,6224.05 h60
  text "7.874" at 12667.32,6102.36 h60
  text "MIN. CLEARANCE:" at 11737.46,6099.92 h60
  text "MIL" at 12988.46,6099.92 h60
  text "MIN. VIA PAD SIZE:" at 11737.46,5975.8 h60
  text "24" at 12803.71,5975.8 h60
  text "MIL" at 12988.46,5975.8 h60
  text "0.05mm (2MIL)" at 12432.46,5845.9 h60
  text "MINIMUM ANNULAR RING" at 11408.23,5837.67 h60
  text "EXTERNAL" at 13140.46,5837.67 h60
  text "PER" at 11608.23,5727.55 h60
  text "IPC-D-275 CLASS 2 LEVEL C" at 11828.23,5727.54 h60
  text "MIL, HOLES" at 13316.46,5627.07 h60
  text "+/-" at 12924,5618.48 h60
  text "+/-" at 13778,5618.48 h60
  text "REGISTRATION TOLERANCES:" at 11408.23,5617.42 h60
  text "METAL" at 12608,5617.42 h60
  text "5" at 13184.2,5617.42 h60
  text "3" at 14017.2,5617.42 h60
  text "MIL" at 14133.46,5617.42 h60
  text "HOLE SIZE TOLERANCE (UNLESS OTHERWISE SPECIFIED):" at 11408.23,5519.1 h60
  text "+/-" at 13778,5516.23 h60
  text "3" at 14017.2,5515.17 h60
  text "MIL" at 14133.46,5515.17 h60
  text "MATERIAL:" at 11333.46,5377.52 h60
  text "FR-4 High Tg" at 12319.9,5249 h60
  text "X" at 12175.46,5241.01 h60
  text "FR-408" at 11754.46,5236.49 h60
  text "OTHER" at 13242.46,5236.49 h60
  text "62 MIL (1.6mm) +/-10%" at 12074.56,5093.46 h60
  text "X" at 11954.46,5091.01 h60
  text "THICKNESS:" at 11408.23,5085.24 h60
  text "OTHER" at 13359.46,5085.24 h60
  text "TOLERANCE:" at 11408.23,4946.92 h60
  text "X" at 12256.46,4946.92 h60
  text "ANSI IPC-6012 TYPE 3 CLASS 2" at 12434.48,4946.92 h60
  text "OTHER +/-" at 12434.46,4802.73 h60
  text "BOW & TWIST:" at 11408.23,4657.54 h60
  text "X" at 12256.46,4657.54 h60
  text "ANSI IPC-6012 TYPE 3 CLASS 2" at 12434.48,4657.54 h60
  text "OTHER +/-" at 12434.46,4510.85 h60
  text "DRILLING:" at 11333.46,4380.23 h60
  text "NC_DRILL FILES" at 13094.46,4275.04 h60
  text "REFERENCE:" at 11408.23,4271.1 h60
  text "X" at 12065.46,4271.01 h60
  text "AS SHOWN" at 12243.46,4271.1 h60
  text "X" at 12966.46,4271.1 h60
  text "OTHER" at 13392.46,4128.85 h60
  text "PTH COPPER THICKNESS:" at 11407.91,4125.32 h60
  text "X" at 12547.14,4125.32 h60
  text "20-30 um" at 12675.14,4125.32 h60
  text "BOARD FINISH:" at 11333.46,3977.73 h60
  text "SILKSCREEN:" at 11488.68,3867.6 h60
  text "X" at 12446.46,3867.6 h60
  text "TOP" at 12563.46,3867.6 h60
  text "X" at 12956.46,3867.6 h60
  text "BOTTOM" at 13074.46,3867.6 h60
  text "SILKSCREEN COLOR:" at 11488.68,3712.41 h60
  text "X" at 12445.46,3712.41 h60
  text "WHITE" at 12563.46,3712.41 h60
  text "OTHER" at 13074.46,3712.41 h60
  text "X" at 12576.46,3568.96 h60
  text "GREEN" at 12694.46,3568.96 h60
  text "OTHER" at 13312.46,3568.96 h60
  text "SOLDER RESIST COLOR:" at 11488.68,3562.1 h60
  text "X" at 12576.46,3414.71 h60
  text "MATTE" at 12694.46,3414.71 h60
  text "SEMI-GLOSS" at 13312,3414.07 h60
  text "IMMERSION GOLD (ENIG)" at 12394.46,3241.94 h60
  text "ENEPIG" at 13732,3234.72 h60
  text "SURFACE FINISH:" at 11333.46,3233.72 h60
  text "X" at 12216.46,3233.72 h60
  text "IMM. TIN/SILVER OR EQUIV" at 11663,3096.4 h60
  text "OTHER" at 13094.46,3092.47 h60
  text "ARRAY/PANEL:" at 11333.46,2937.09 h60
  text "CUT AND TRIM PER M1 BOARD OUTLINE" at 12394.46,2928.87 h60
  text "N.C. ROUTE" at 12394.46,2792.9 h60
  text "X" at 13082.46,2792.9 h60
  text "V. SCORE" at 13260.46,2792.9 h60
  text "CERTIFICATION:" at 11333.46,2663.77 h60
  text "MATERIALS AND WORKMANSHIP FOR ALL PCBS" at 12058.46,2663.77 h60
  text "TO MEET OR EXCEED THE REQUIREMENTS OF:" at 12058.46,2569.71 h60
  text "X" at 11695.97,2441.08 h60
  text "ANSI IPC-A-600F CLASS ->" at 11823.96,2441.08 h60
  text "X" at 13471.97,2441.08 h60
  text "2" at 13581.96,2441.08 h60
  text "1" at 13266.96,2439.58 h60
  text "3" at 13935.96,2439.58 h60
  text "X" at 12507.97,2293.39 h60
  text "RoHS" at 12635.96,2293.39 h60
  text "OTHER" at 13280.36,2293.39 h60
  text "PER ORDER" at 13677.42,2293.39 h60
  text "ALL BOARDS MUST MEET OR EXCEED UL94-V0 REQUIREMENTS." at 11361,2139.57 h60
  text "PCB MUST BEAR THE UL94V-0 UL REGISTERED MATERIAL ID NUMBER" at 11361,2023.5 h60
  text "ADDITIONAL REQUIREMENTS:" at 11333.46,1854.08 h60
  text "MICROSECTION:" at 11408.23,1746.95 h60
  text "YES" at 12313.96,1746.95 h60
  text "REQUIRED" at 13175.46,1602.62 h60
  text "BARE BOARD ELEC. TEST:" at 11408.23,1599.76 h60
  text "NONE" at 12713.96,1599.76 h60
  text "X" at 13057.46,1599.76 h60
  text "PER ORDER" at 13767.46,1599.76 h60
  text "XX MIL VIAS REQUIRE NON-CONDUCTIVE FILL AND PLANARIZE" at 11576.38,1394.82 h59
  text "XX MIL VIAS REQUIRE CONDUCTIVE FILL AND PLANARIZE" at 11584.38,1290.84 h60
  text "OUTER XX MIL TRACES REQUIRE 50 OHM SINGLE-ENDED IMPEDANCE" at 11583.39,1127.46 h58
  text "LAYER 2 & 3 (INNER LAYERS) XX MIL WIDE, XX MIL SPACE / TRACES REQUIRE 100 OHM DIFFERENTIAL IMPEDANCE" at 11575.39,891.74 h60
  text ".Layer_Name" at 577,-858.49 h60
M11 Gerber Information:
  lines w10: -292,-930.17 6308,-930.17 ; -292,-726.83 6310,-726.83 ; -292,-523.5 -292,-1133.5 3713,-1133.5 6310,-1133.5 6310,-523.5 -291.5,-523.5 -291.5,-1133.5 1284,-1133.5 ; 2173,-1133.5 2173,-523.5 ; 3440,-726.83 3440,-523.5 ; 4280,-726.83 4280,-523.5 ; 4902,-1140 4902,-937.17
  text "ALL ARTWORK VIEWED FROM TOP SIDE" at -228.5,-655.67 h60
  text "BOARD #:" at 2248,-655.67 h60
  text ".PRJ_Number" at 2793.5,-655.67 h60
  text "REV:" at 3638,-655.67 h60
  text ".PCB_Rev" at 3929.5,-655.67 h60
  text "SVN REV:" at 4476,-655.67 h60
  text ".VersionControl_RevNumber" at 4982,-655.67 h60
  text "LAYER NAME =" at -228.5,-858.49 h60
  text "TID #:" at 2248,-859 h60
  text ".TID" at 2793.5,-859 h60
  text "PLOT NAME =" at -228.5,-1064.34 h60
  text ".plot_File_Name" at 577,-1064.34 h60
  text "GENERATED    :" at 2250,-1064.34 h60
  text ".Print_Date" at 3119.5,-1064.34 h60
  text ".Print_Time" at 3848.5,-1064.34 h60
  text "TEXAS INSTRUMENTS" at 5113,-1064.34 h60
M12 Stackup:
  drawing of 191 lines, arcs and shapes, not listed
  text "Layer" at 9821.59,7717.44 h60
  text "Name" at 10231.51,7717.44 h60
  text "Material" at 11161.25,7717.44 h60
  text "Thickness" at 12021.02,7717.44 h60
  text "Constant" at 12670.85,7717.44 h60
  text "Board Layer Stack" at 13240.71,7717.44 h60
  text "Top Overlay" at 10231.51,7597.44 h60
  text "Top Solder" at 10231.51,7477.44 h60
  text "Solder Resist" at 11161.25,7477.44 h60
  text "0.40mil" at 12021.02,7477.44 h60
  text "3.5" at 12670.85,7477.44 h60
  text "1" at 9821.59,7357.44 h60
  text "Top Layer" at 10231.51,7357.44 h60
  text "1.40mil" at 12021.02,7357.44 h60
  text "Dielectric1" at 10231.51,7237.44 h60
  text "FR-4 High Tg" at 11161.25,7237.44 h60
  text "59.20mil" at 12021.02,7237.44 h60
  text "4.8" at 12670.85,7237.44 h60
  text "2" at 9821.59,7117.44 h60
  text "Bottom Layer" at 10231.51,7117.44 h60
  text "1.40mil" at 12021.02,7117.44 h60
  text "Bottom Solder" at 10231.51,6997.44 h60
  text "Solder Resist" at 11161.25,6997.44 h60
  text "0.40mil" at 12021.02,6997.44 h60
  text "3.5" at 12670.85,6997.44 h60
  text "Bottom Overlay" at 10231.51,6877.44 h60
  text ".Layer_Name" at 577,-858.49 h60
M13 Component Bodies Top:
  text ".Layer_Name" at 577,-858.49 h60
M14 Component Bodies Bottom:
  text ".Layer_Name" at 577,-858.49 h60
M15 Courtyards Top:
  text ".Layer_Name" at 577,-858.49 h60
M16 Courtyards Bottom:
  text ".Layer_Name" at 577,-858.49 h60
Drill Drawing:
  text ".Layer_Name" at 577,-858.49 h60
M17 Embedded Cavity:
  text ".Layer_Name" at 577,-858.49 h60
M18 Embedded Assembly:
  text ".Layer_Name" at 577,-858.49 h60
M19 Embedded Keepout:
  text ".Layer_Name" at 577,-858.49 h60

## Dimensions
0,-400 to 1000,-400 on M2 Board Dimensions
0,0 to 2210,0 on M2 Board Dimensions
0,0 to 0,1500 on M2 Board Dimensions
